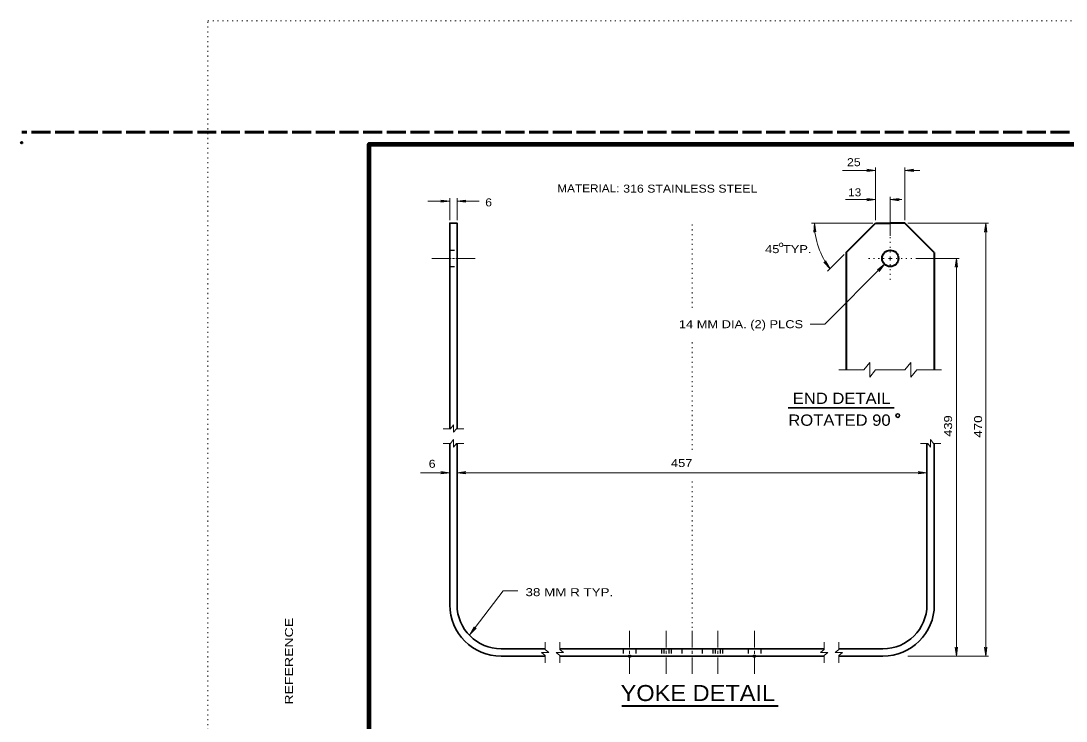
# Model space of a CAD drawing. Extents: x 312583 to 312854, y 144419 to 144597.
# Drawn here: x 312583.5 to 312682.7, y 144530.3 to 144596.8 of the extents above; entities that cross this region are included whole.
import ezdxf
from ezdxf.enums import TextEntityAlignment as Align

# ---------------------------------------------------------------- set-up
doc = ezdxf.new("R2010")
doc.units = 0
doc.header["$LTSCALE"] = 0.3
doc.header["$PDMODE"] = 32
doc.header["$PDSIZE"] = 0.15
for name, pattern in [('DOTTED', [1.5, 0.3, -1.2]), ('LONG_DASHED', [7.5, 6, -1.5]), ('SHORT_DASHED', [2.7, 1.5, -1.2])]:
    doc.linetypes.add(name, pattern=pattern)
for name, color, linetype, lineweight in [('1', 7, 'Continuous', 40), ('2', 7, 'Continuous', 13), ('63', 7, 'DOTTED', 13)]:
    doc.layers.add(name, color=color, linetype=linetype, lineweight=lineweight)

msp = doc.modelspace()

# ---------------------------------------------------------------- linework, layer by layer
at = {"layer": '1', "linetype": 'DOTTED', "lineweight": 13}
for p, q in [((312647.1599, 144569.532), (312647.1599, 144577.5786)), ((312647.1599, 144556.043), (312647.1599, 144566.3521)), ((312647.1599, 144539.138), (312647.1599, 144553.26))]:
    msp.add_line(p, q, dxfattribs=at)
at = {"layer": '1'}
for p, q in [((312661.7956, 144574.788), (312664.5862, 144577.5786)), ((312664.5862, 144577.5786), (312665.9816, 144577.5786)), ((312667.3769, 144577.5786), (312665.9816, 144577.5786)), ((312670.1599, 144574.788), (312667.3769, 144577.5786)), ((312661.7956, 144574.788), (312661.7956, 144563.6406)), ((312670.1599, 144574.788), (312670.1599, 144563.6406))]:
    msp.add_line(p, q, dxfattribs=at)
at = {"layer": '1', "linetype": 'SHORT_DASHED', "lineweight": 25}
for p, q in [((312624.1599, 144575.0103), (312624.8576, 144575.0103)), ((312624.1599, 144573.454), (312624.8576, 144573.454)), ((312640.6356, 144537.1523), (312640.6356, 144536.4546)), ((312641.8392, 144537.1523), (312641.8392, 144536.4546)), ((312644.2619, 144537.1523), (312644.2619, 144536.4546)), ((312644.4919, 144537.1523), (312644.4919, 144536.4546)), ((312644.9596, 144537.1523), (312644.9596, 144536.4546)), ((312645.1896, 144537.1523), (312645.1896, 144536.4546)), ((312646.2016, 144537.1523), (312646.2016, 144536.4546)), ((312648.1259, 144537.1523), (312648.1259, 144536.4546)), ((312649.1379, 144537.1523), (312649.1379, 144536.4546)), ((312649.3679, 144537.1523), (312649.3679, 144536.4546)), ((312649.8356, 144537.1523), (312649.8356, 144536.4546)), ((312650.0656, 144537.1523), (312650.0656, 144536.4546)), ((312652.4882, 144537.1523), (312652.4882, 144536.4546)), ((312653.6842, 144537.1523), (312653.6842, 144536.4546))]:
    msp.add_line(p, q, dxfattribs=at)
at = {"layer": '1', "lineweight": 158}
msp.add_lwpolyline([(312616.5, 144423.1446), (312616.5, 144585.0846), (312849, 144585.0846)], dxfattribs=at)
at = {"layer": '1'}
msp.add_circle((312665.9809, 144574.2311), 0.7806, dxfattribs=at)
for p in [(312583.526, 144585.2246), (312641.2412, 144536.4546), (312653.0862, 144536.4546)]:
    msp.add_point(p, dxfattribs=at)
at = {"layer": '2'}
for p, q in [((312664.5862, 144577.8546), (312664.5862, 144582.8763)), ((312667.3769, 144577.8546), (312667.3769, 144582.8763)), ((312664.5862, 144582.5926), (312661.4556, 144582.5926)), ((312663.7506, 144582.7), (312664.0189, 144582.5926)), ((312664.5862, 144582.5926), (312663.7506, 144582.7)), ((312663.7506, 144582.493), (312664.0189, 144582.5926)), ((312664.5862, 144582.5926), (312663.7506, 144582.493)), ((312667.3769, 144582.5926), (312668.2126, 144582.7)), ((312668.7722, 144582.5926), (312667.3769, 144582.5926)), ((312667.3769, 144582.5926), (312668.2126, 144582.493)), ((312668.2126, 144582.7), (312667.9442, 144582.5926)), ((312668.2126, 144582.493), (312667.9442, 144582.5926)), ((312624.1599, 144577.8546), (312624.1599, 144579.9476)), ((312624.8576, 144577.8546), (312624.8576, 144579.9476)), ((312663.7506, 144579.9093), (312664.0189, 144579.8096)), ((312664.5862, 144579.8096), (312663.7506, 144579.9093)), ((312665.9816, 144576.3673), (312665.9816, 144580.0856)), ((312665.9816, 144579.8096), (312666.8172, 144579.9093)), ((312666.8172, 144579.9093), (312666.5489, 144579.8096)), ((312624.1599, 144579.664), (312622.0746, 144579.664)), ((312623.3242, 144579.7713), (312623.5926, 144579.664)), ((312624.1599, 144579.664), (312623.3242, 144579.7713)), ((312623.3242, 144579.5643), (312623.5926, 144579.664)), ((312624.1599, 144579.664), (312623.3242, 144579.5643)), ((312624.8576, 144579.664), (312625.7009, 144579.7713)), ((312624.8576, 144579.664), (312626.9506, 144579.664)), ((312624.8576, 144579.664), (312625.7009, 144579.5643)), ((312625.7009, 144579.7713), (312625.4326, 144579.664)), ((312625.7009, 144579.5643), (312625.4326, 144579.664)), ((312664.5862, 144579.8096), (312661.7391, 144579.8096)), ((312663.7506, 144579.7023), (312664.0189, 144579.8096)), ((312664.5862, 144579.8096), (312663.7506, 144579.7023)), ((312667.0932, 144579.8096), (312665.9816, 144579.8096)), ((312665.9816, 144579.8096), (312666.8172, 144579.7023)), ((312666.8172, 144579.7023), (312666.5489, 144579.8096)), ((312664.3102, 144577.5786), (312658.5066, 144577.5786)), ((312658.7749, 144577.5786), (312658.7212, 144576.7353)), ((312658.7212, 144576.7353), (312658.8132, 144577.0036)), ((312658.7749, 144577.5786), (312658.9282, 144576.743)), ((312658.9282, 144576.743), (312658.8132, 144577.0036)), ((312667.6529, 144577.5786), (312675.3196, 144577.5786)), ((312675.0436, 144577.5786), (312674.9362, 144576.7353)), ((312674.9362, 144576.7353), (312675.0436, 144577.0036)), ((312675.0436, 144536.4546), (312675.0436, 144577.5786)), ((312675.0436, 144577.5786), (312675.1432, 144576.7353)), ((312675.1432, 144576.7353), (312675.0436, 144577.0036)), ((312624.3056, 144574.2283), (312622.4656, 144574.2283)), ((312624.6046, 144574.2283), (312624.4206, 144574.2283)), ((312624.7272, 144574.2283), (312626.5596, 144574.2283)), ((312659.6796, 144573.868), (312659.9249, 144573.7146)), ((312660.2622, 144573.2546), (312659.6796, 144573.868)), ((312659.8482, 144573.9906), (312659.9249, 144573.7146)), ((312660.2622, 144573.2546), (312659.8482, 144573.9906)), ((312661.5962, 144574.5963), (312660.0246, 144573.017)), ((312661.5962, 144574.5963), (312660.0246, 144573.017)), ((312665.9816, 144574.2283), (312665.7976, 144574.2283)), ((312665.9816, 144574.2283), (312665.9816, 144574.42)), ((312665.9816, 144574.2283), (312665.9816, 144574.0443)), ((312665.9816, 144574.2283), (312666.1656, 144574.2283)), ((312668.3966, 144574.2283), (312672.5289, 144574.2283)), ((312672.2529, 144574.2283), (312672.1532, 144573.3926)), ((312672.2529, 144536.4546), (312672.2529, 144574.2283)), ((312672.2529, 144574.2283), (312672.3602, 144573.3926)), ((312665.4296, 144573.6686), (312659.7792, 144567.9953)), ((312665.4296, 144573.6686), (312664.7626, 144573.1473)), ((312664.7626, 144573.1473), (312665.0309, 144573.2623)), ((312665.4296, 144573.6686), (312664.9159, 144572.994)), ((312664.9159, 144572.994), (312665.0309, 144573.2623)), ((312672.1532, 144573.3926), (312672.2529, 144573.661)), ((312672.3602, 144573.3926), (312672.2529, 144573.661)), ((312658.3839, 144567.9953), (312659.7792, 144567.9953)), ((312661.1056, 144563.6406), (312663.4746, 144563.6406)), ((312665.9816, 144563.6406), (312667.3769, 144563.6406)), ((312623.5389, 144558.0593), (312624.2289, 144558.0593)), ((312623.5389, 144556.664), (312624.2289, 144556.664)), ((312670.7886, 144556.664), (312670.0909, 144556.664)), ((312624.1599, 144553.881), (312621.3769, 144553.881)), ((312623.3242, 144553.9806), (312623.5926, 144553.881)), ((312624.1599, 144553.881), (312623.3242, 144553.9806)), ((312623.3242, 144553.7736), (312623.5926, 144553.881)), ((312624.1599, 144553.881), (312623.3242, 144553.7736)), ((312624.8576, 144553.881), (312625.7009, 144553.9806)), ((312624.8576, 144553.881), (312669.4622, 144553.881)), ((312624.8576, 144553.881), (312625.7009, 144553.7736)), ((312625.7009, 144553.9806), (312625.4326, 144553.881)), ((312625.7009, 144553.7736), (312625.4326, 144553.881)), ((312668.6266, 144553.9806), (312668.8949, 144553.881)), ((312669.4622, 144553.881), (312668.6266, 144553.9806)), ((312668.6266, 144553.7736), (312668.8949, 144553.881)), ((312669.4622, 144553.881), (312668.6266, 144553.7736)), ((312626.0612, 144538.5016), (312626.4906, 144539.23)), ((312626.4906, 144539.23), (312626.4139, 144538.954)), ((312626.0612, 144538.5016), (312626.6592, 144539.1073)), ((312626.6592, 144539.1073), (312626.4139, 144538.954)), ((312641.2412, 144537.2673), (312641.2412, 144538.8543)), ((312644.7219, 144537.2673), (312644.7219, 144538.8543)), ((312647.1599, 144537.2673), (312647.1599, 144538.8543)), ((312649.6056, 144537.2673), (312649.6056, 144538.8543)), ((312653.0862, 144537.2673), (312653.0862, 144538.8543)), ((312633.2219, 144537.781), (312633.2219, 144537.0833)), ((312634.6172, 144537.781), (312634.6172, 144537.0833)), ((312659.7102, 144537.781), (312659.7102, 144537.0833)), ((312661.1056, 144537.781), (312661.1056, 144537.0833)), ((312672.1532, 144537.298), (312672.2529, 144537.0296)), ((312672.2529, 144536.4546), (312672.1532, 144537.298)), ((312672.3602, 144537.298), (312672.2529, 144537.0296)), ((312672.2529, 144536.4546), (312672.3602, 144537.298)), ((312674.9362, 144537.298), (312675.0436, 144537.0296)), ((312675.0436, 144536.4546), (312674.9362, 144537.298)), ((312675.1432, 144537.298), (312675.0436, 144537.0296)), ((312675.0436, 144536.4546), (312675.1432, 144537.298)), ((312641.2412, 144536.6616), (312641.2412, 144536.9606)), ((312641.2412, 144536.332), (312641.2412, 144534.768)), ((312644.7219, 144536.6616), (312644.7219, 144536.9606)), ((312644.7219, 144536.332), (312644.7219, 144534.768)), ((312647.1599, 144536.6616), (312647.1599, 144536.9606)), ((312647.1599, 144536.332), (312647.1599, 144534.768)), ((312649.6056, 144536.6616), (312649.6056, 144536.9606)), ((312649.6056, 144536.332), (312649.6056, 144534.768)), ((312653.0862, 144536.6616), (312653.0862, 144536.9606)), ((312653.0862, 144536.332), (312653.0862, 144534.768)), ((312667.6529, 144536.4546), (312675.3196, 144536.4546))]:
    msp.add_line(p, q, dxfattribs=at)
at = {"layer": '2', "linetype": 'DOTTED'}
for p, q in [((312665.9816, 144574.7803), (312665.9816, 144576.3673)), ((312665.4066, 144574.2283), (312663.8426, 144574.2283)), ((312666.5489, 144574.2283), (312668.1206, 144574.2283)), ((312665.9816, 144573.6763), (312665.9816, 144572.0893))]:
    msp.add_line(p, q, dxfattribs=at)
at = {"layer": '2', "lineweight": 35}
for p, q in [((312656.2809, 144560.0507), (312666.3442, 144560.0507)), ((312624.1599, 144541.3306), (312624.1599, 144556.664)), ((312624.8576, 144541.3306), (312624.8576, 144556.664)), ((312669.4622, 144541.3306), (312669.4622, 144556.664)), ((312670.1599, 144541.3306), (312670.1599, 144556.664)), ((312629.0436, 144537.1523), (312633.2219, 144537.1523)), ((312634.6172, 144537.1523), (312647.1599, 144537.1523)), ((312659.7102, 144537.1523), (312647.1599, 144537.1523)), ((312665.2839, 144537.1523), (312661.1056, 144537.1523)), ((312629.0436, 144536.4546), (312633.2219, 144536.4546)), ((312634.6172, 144536.4546), (312647.1599, 144536.4546)), ((312659.7102, 144536.4546), (312647.1599, 144536.4546)), ((312665.2839, 144536.4546), (312661.1056, 144536.4546))]:
    msp.add_line(p, q, dxfattribs=at)
at = {"layer": '2', "lineweight": 40}
msp.add_line((312640.4879, 144531.7516), (312655.3347, 144531.7516), dxfattribs=at)
at = {"layer": '2', "lineweight": 35}
msp.add_lwpolyline([(312624.8576, 144558.0593), (312624.8576, 144577.5786), (312624.1599, 144577.5786), (312624.1599, 144558.0593)], dxfattribs=at)
at = {"layer": '2'}
for points in [[(312663.4746, 144563.6406), (312664.0266, 144564.3306), (312664.0266, 144562.943), (312664.5862, 144563.6406), (312665.9816, 144563.6406)], [(312667.3769, 144563.6406), (312667.9289, 144564.3306), (312667.9289, 144562.943), (312668.4886, 144563.6406), (312670.8576, 144563.6406)], [(312624.2289, 144558.0593), (312624.5126, 144558.412), (312624.5126, 144557.7143), (312624.7886, 144558.0593), (312625.4862, 144558.0593)], [(312624.2289, 144556.664), (312624.5126, 144557.0166), (312624.5126, 144556.319), (312624.7886, 144556.664), (312625.4862, 144556.664)], [(312670.0909, 144556.664), (312669.8149, 144557.0166), (312669.8149, 144556.319), (312669.5389, 144556.664), (312668.8412, 144556.664)], [(312626.0612, 144538.5016), (312629.2352, 144542.6493), (312630.6306, 144542.6493)], [(312633.2219, 144537.0833), (312633.5746, 144536.8073), (312632.8769, 144536.8073), (312633.2219, 144536.5236), (312633.2219, 144535.826)], [(312634.6172, 144537.0833), (312634.9622, 144536.8073), (312634.2722, 144536.8073), (312634.6172, 144536.5236), (312634.6172, 144535.826)], [(312659.7102, 144537.0833), (312659.3576, 144536.8073), (312660.0552, 144536.8073), (312659.7102, 144536.5236), (312659.7102, 144535.826)], [(312661.1056, 144537.0833), (312660.7529, 144536.8073), (312661.4506, 144536.8073), (312661.1056, 144536.5236), (312661.1056, 144535.826)]]:
    msp.add_lwpolyline(points, dxfattribs=at)
msp.add_circle((312655.6209, 144575.5218), 0.1743, dxfattribs=at)
at = {"layer": '2', "lineweight": 35}
msp.add_circle((312666.6972, 144559.3103), 0.1743, dxfattribs=at)
at = {"layer": '2'}
msp.add_arc((312665.9167, 144577.6239), 7.1407, 180.38032, 217.69931, dxfattribs=at)
at = {"layer": '2', "lineweight": 35}
for centre, radius, start, end in [((312629.0415, 144541.3341), 4.8788, 180, 270), ((312629.0415, 144541.3341), 4.1818, 180, 270), ((312665.2839, 144541.3341), 4.1818, 270, 0), ((312665.2839, 144541.3341), 4.8788, 270, 0)]:
    msp.add_arc(centre, radius, start, end, dxfattribs=at)
at = {"layer": '63'}
for p, q in [((312601.2, 144596.7846), (312853.5, 144596.7846)), ((312601.2, 144418.5846), (312601.2, 144596.7846))]:
    msp.add_line(p, q, dxfattribs=at)
at = {"layer": '63', "linetype": 'LONG_DASHED', "lineweight": 60}
msp.add_line((312851.75, 144586.2246), (312583.526, 144586.2246), dxfattribs=at)

# ---------------------------------------------------------------- texts
at = {"layer": '1', "width": 1.3}
msp.add_text('REFERENCE                                                              ', height=0.7682, rotation=90, dxfattribs=at).set_placement((312609.2854, 144531.8549))
at = {"layer": '2'}
for s, width, p in [('25 ', 1.15, (312661.8738, 144582.9865)), ('MATERIAL:', 1.1, (312634.3718, 144580.5032)), ('316 STAINLESS STEEL', 1.15, (312640.6313, 144580.4768)), ('13 ', 1.1, (312661.982, 144580.1249)), ('6 ', 1.15, (312627.5273, 144579.1695)), ('45 TYP.', 1.2, (312654.0982, 144574.7291)), ('14 MM DIA. (2) PLCS', 1.2, (312645.9138, 144567.6009)), ('6 ', 1.15, (312622.1652, 144554.3458)), ('457 ', 1.2, (312645.1621, 144554.4166)), ('38 MM R TYP.', 1.25, (312631.3555, 144542.1533))]:
    msp.add_text(s, height=0.76, dxfattribs=dict(at, width=width)).set_placement(p)
at = {"layer": '2', "width": 1.1}
for s, height, p in [('END DETAIL', 1.07, (312661.3625, 144560.4059)), ('ROTATED 90', 1.07, (312661.1606, 144558.336)), ('YOKE DETAIL', 1.52, (312647.7144, 144532.1959))]:
    msp.add_text(s, height=height, dxfattribs=at).set_placement(p, align=Align.CENTER)
at = {"layer": '2'}
for s, width, p in [('439 ', 1.2, (312671.8489, 144557.2925)), ('470 ', 1.25, (312674.698, 144557.1978))]:
    msp.add_text(s, height=0.76, rotation=90, dxfattribs=dict(at, width=width)).set_placement(p)

doc.saveas('drawing.dxf')
